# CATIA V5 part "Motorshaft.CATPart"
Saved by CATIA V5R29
Part number: Motorshaft
Bounding box of the stored display mesh (mm): x -7.25 to 7.25, y -120 to 120, z -7.223 to 7.223
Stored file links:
  D:\Abhinav\2019\3rd Session\CATIA V5 2019\RESOURCES\CATIA_RESOURCES\Tutorial Files\Tutorials\Tutorials\c12_catia_v5_6r2019_tut\c12Tut1\Motorshaft.CATPart
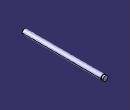
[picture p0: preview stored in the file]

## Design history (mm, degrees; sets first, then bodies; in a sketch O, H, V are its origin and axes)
Body1 (main body)
  Sketch1 on zx-plane, origin (0, 0, 0), H (-1, 0, 0), V (0, 0, 1)
    circle A1 centre (0, 0) radius 7.25
    radius A1 = 7.25
  Pad1: profile Sketch1, direction (0, 1, 0), length 120, mirrored extent
  Sketch2 on yz-plane, origin (0, 0, 0), H (0, 1, 0), V (0, 0, 1)
    line L1 (113.2, 6) -> (115, 6)
    line L2 (115, 6) -> (115, 7.25)
    line L3 (115, 7.25) -> (113.2, 7.25)
    line L4 (113.2, 7.25) -> (113.2, 6)
    reference projected line E1 (120, 7.25) -> (120, -7.25) from edge of Pad1
    reference projected line E2 through (0, 0) direction (1, 0) from axis of face of Pad1 from Sketch1.A1
    distance E1 L2 = 5
    distance H L3 = 7.25
    length L1 = 1.8
    distance L1 E2 = 6
    horizontal: L1 H, L3 H
    vertical: L2 V, L4 V
  Groove1: profile Sketch2, axis axis of face of Pad1, angle 360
